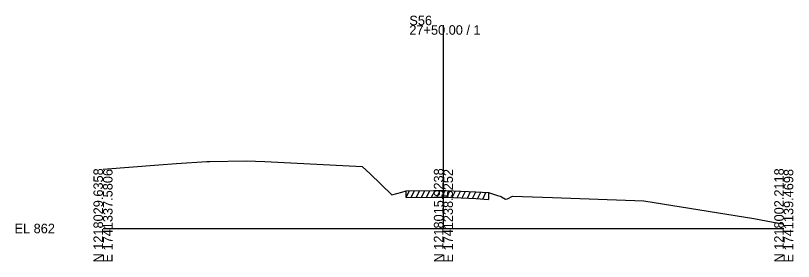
# Model space of a CAD drawing. Extents: x -26 to 1203, y -10 to 19541.
# Drawn here: x -25.7 to 202.8, y 2490.3 to 2562.6 of the extents above; entities that cross this region are included whole.
import ezdxf

# ---------------------------------------------------------------- set-up
doc = ezdxf.new("R2010")
doc.units = 0
for name, color, linetype in [('RD_GPK_XS_Cell', 7, 'Continuous'), ('RD_XS_ExGround', 7, 'Continuous'), ('RD_XS_ExPaveRet', 7, 'Continuous'), ('RD_XS_TX_Elev_EX', 7, 'Continuous')]:
    doc.layers.add(name, color=color, linetype=linetype)

msp = doc.modelspace()

# ---------------------------------------------------------------- linework, layer by layer
at = {"layer": 'RD_GPK_XS_Cell'}
for p, q in [((100, 2500), (100, 2559.76)), ((0, 2500), (100, 2500)), ((100, 2500), (200, 2500))]:
    msp.add_line(p, q, dxfattribs=at)
at = {"layer": 'RD_XS_ExGround'}
msp.add_lwpolyline([(0, 2517.42), (16.38, 2518.76), (21.6, 2519.11), (30.53, 2519.71), (31.39, 2519.74), (42.1, 2519.92), (47.57, 2519.65), (76.14, 2518.24), (78.51, 2516.02), (84.85, 2509.89), (87.81, 2510.71), (89.04, 2511.11), (97.21, 2511.16), (100, 2511.2), (100.78, 2511.21), (109.56, 2510.79), (113.22, 2510.55), (115.88, 2509.74), (116.67, 2509.5), (117.04, 2509.31), (118.22, 2508.57), (118.8, 2508.73), (120.32, 2509.54), (132.06, 2509.15), (158.92, 2508.15), (191.18, 2502.96), (200, 2501.27)], dxfattribs=at)
at = {"layer": 'RD_XS_ExPaveRet'}
for p, q in [((89.04, 2509.11), (90.04, 2511.12)), ((89.04, 2509.11), (89.04, 2511.11)), ((90.54, 2509.12), (91.54, 2511.13)), ((92.04, 2509.13), (93.04, 2511.14)), ((93.54, 2509.14), (94.54, 2511.15)), ((95.04, 2509.15), (96.04, 2511.16)), ((96.54, 2509.16), (97.54, 2511.17)), ((98.04, 2509.17), (99.04, 2511.19)), ((99.54, 2509.19), (100.54, 2511.21)), ((101.04, 2509.2), (102.01, 2511.15)), ((102.54, 2509.13), (103.51, 2511.08)), ((104.04, 2509.05), (105.01, 2511.01)), ((105.54, 2508.98), (106.51, 2510.94)), ((107.04, 2508.91), (108.01, 2510.86)), ((108.54, 2508.84), (109.51, 2510.79)), ((110.04, 2508.76), (111, 2510.69)), ((111.54, 2508.66), (112.5, 2510.59)), ((113.22, 2510.55), (113.22, 2508.55)), ((89.04, 2509.11), (97.21, 2509.16)), ((97.21, 2509.16), (100, 2509.2)), ((100, 2509.2), (100.78, 2509.21)), ((100.78, 2509.21), (109.56, 2508.79)), ((109.56, 2508.79), (113.22, 2508.55))]:
    msp.add_line(p, q, dxfattribs=at)

# ---------------------------------------------------------------- texts
at = {"layer": 'RD_GPK_XS_Cell'}
for s, p in [('S56', (90, 2559.76)), ('27+50.00 / 1', (90, 2556.96)), ('EL 862', (-26, 2498.6))]:
    msp.add_text(s, height=2.8, dxfattribs=at).set_placement(p)
for s, p in [('N 1218029.6358', (0, 2490)), ('E 1741337.5806', (2.8, 2490)), ('N 1218015.9238', (100, 2490)), ('E 1741238.5252', (102.8, 2490)), ('N 1218002.2118', (200, 2490)), ('E 1741139.4698', (202.8, 2490))]:
    msp.add_text(s, height=2.8, rotation=90, dxfattribs=at).set_placement(p)
at = {"layer": 'RD_XS_TX_Elev_EX'}
msp.add_text('867.60', height=0.1, rotation=90, dxfattribs=at).set_placement((100.1, 2511.2))

doc.saveas('drawing.dxf')
